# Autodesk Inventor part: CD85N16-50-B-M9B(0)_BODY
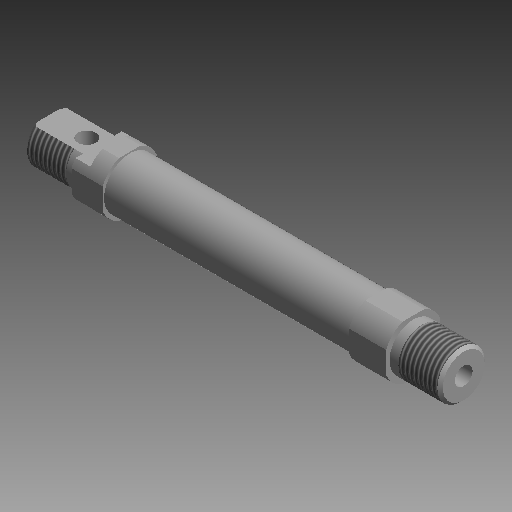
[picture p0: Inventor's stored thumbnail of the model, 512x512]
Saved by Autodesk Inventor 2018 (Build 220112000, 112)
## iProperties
Category: PARTsolutions
Company: SMC
Part Number: CD85N16-50-B-M9B(0)_BODY
Material: Generic
Catalog Web Link: www.cadenas.de
Description: C85/CD85 BODY-ISO Standard Air Cylinder:Standard Type Double Acting Single Rod
Vendor: SMC
Document SubType Name: Modeling
Designer: partserver
Manufacturer: SMC
Mass: 19.9773 g
Surface Area: 122.047 cm^2
Volume: 19.9773 cm^3
Density: 1 g/cm^3
Appearance: PSOLRGB-192-192-192
PSOL_IDENT_0: {$CADENAS_DATA\23d-libs\smc_jp\actuator\standard_air_cylinder\c85\c85\parts\c85_body.prj},247 {VTYP=
PSOL_IDENT_1: 3D},{NB=CD85N16-50-B-M9B(0)_BODY},{LINA=CD85N16-50-B-M9B_BODY},{NN=C85/CD85 BODY},{DATE=09.12.2020 0
PSOL_IDENT_2: 3:32:12},{GEOMDATE=26.04.2020 06:36:00},{VERSION=},{LINEID=90},{WBVAR=MAGNET,AUTOSW,STROKE,CUSHION,B
PSOL_IDENT_3: OOT,SWITCHMT,THREAD},{WBNUMERIC=STROKE}  {NB=CD85N16-50-B-M9B(0)_BODY},{LINA=CD85N16-50-B-M9B_BODY},
PSOL_IDENT_4: {KT=DUMMY},{ORDER=CD85N16-50-B-M9B},{BORE=16},{MOUNT=(N) Basic (Integral clevis)},{MOUNTX=N},{MAGNET=
PSOL_IDENT_5: D},{AUTOSW=-M9B},{AUTOSWX='','(-) Without auto switch','-M9N','M9N','-M9P','M9P','-M9B','M9B','-M9NV'
PSOL_IDENT_6: ,'M9NV','-M9PV','M9PV','-M9BV','M9BV','-M9NW','M9NW','-M9PW','M9PW','-M9BW','M9BW','-M9NWV','M9NWV','
PSOL_IDENT_7: -M9PWV','M9PWV','-M9BWV','M9BWV','-M9NA','M9NA','-M9PA','M9PA','-M9BA','M9BA','-M9NAV','M9NAV','-M9P
PSOL_IDENT_8: AV','M9PAV','-M9BAV','M9BAV','-A90','A90','-A93','A93','-A96','A96','-A90V','A90V','-A93V','A93V','-
PSOL_IDENT_9: A96V','A96V','-H7C','H7C','-H7NF','H7NF','-C73C','C73C','-C80C','C80C','-J79C','J79C','-F79F','F79F'
PSOL_IDENT_10: ,'-A72','A72','-A72H','A72H','-A73C','A73C','-A80C','A80C','-A79W','A79W'},{STROKE=50},{CUSHION=},{C
PSOL_IDENT_11: USHIONX= '','(-) Rubber bumper(Standard)','C','(C) Air cushion' },{BOOT=},{BOOTX= '','N/A' },{SWITCH
PSOL_IDENT_12: MT=-B},{SWITCHMTX= '-A','(A) Rail mounting','-B','(B) Band mounting' },{THREAD=0},{MAX=400},{MAX1=20
PSOL_IDENT_13: 0},{AM=16},{BE=M16x1.5},{BED=16},{BEJ=1.50},{C=6},{CD=6},{D=19.7},{EE=M5x0.8},{EW=12},{F=17},{G1=8},
PSOL_IDENT_14: {G2=6},{HR=14.0},{N1=12.5},{N2=10.5},{NA=18.3},{ND=16},{RR=13},{S=56},{U=9},{WA=9.5},{D1=17.400},{SW
PSOL_IDENT_15: A=7.5},{SWB=13.5},{SW=2}
NB: CD85N16-50-B-M9B(0)_BODY
NN: C85/CD85 BODY
NT: ISO Standard Air Cylinder:Standard Type Double Acting Single Rod
NBSYN: $ORDER.($THREAD.)_BODY
LINA: CD85N16-50-B-M9B_BODY
CATALOG: SMC (JP
BORE: 16
MOUNT: (N) Basic (Integral clevis)
MAGNET: (D) With magnet
AUTOSW: M9B
STROKE: 50
CUSHION: (-) Rubber bumper(Standard)
BOOT: N/A
SWITCHMT: (B) Band mounting
THREAD: on
MAX: 400
MAX1: 200
AM: 16
BE: M16x1.5
BED: 16
BEJ: 1.5
C: 6
CD: 6
D: 19.7
EE: M5x0.8
EW: 12
F: 17
HR: 14
NA: 18.3
ND: 16
RR: 13
U: 9
WA: 9.5
D1: 17.4
SUPPLIER: SMC
ARTICLENO: CD85N16-50-B-M9B(0)_BODY
BOMINFO: CD85N16-50-B-M9B_BODY
CREATOR: CADENAS GmbH
Title: CD85N16-50-B-M9B_BODY
Author: Cadenas PARTsolutions
Comments: ISO Standard Air Cylinder:Standard Type Double Acting Single Rod
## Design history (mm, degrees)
sketch "Sketch_1"
  geometry: L1 (106, 0)-(-17, 0); L2 (67.5, 0)-(67.5, 8); L3 (67.5, 8)-(12.5, 8); L4 (12.5, 8)-(12.5, 3); L5 (12.5, 3)-(-17, 3); L6 (-17, 3)-(-17, 7.08); L7 (-17, 7.08)-(-16.08, 8); L8 (-16.08, 8)-(0, 8); L9 (0, 8)-(0, 9.85); L10 (0, 9.85)-(12.5, 9.85); L11 (12.5, 9.85)-(12.5, 8.7); L12 (12.5, 8.7)-(95.5, 8.7); L13 (95.5, 8.7)-(95.5, 9.85); L14 (95.5, 9.85)-(106, 9.85); L15 (106, 9.85)-(106, 0); L16 (106, 0)-(67.5, 0)
  constraints: 32 end point
revolve "Revolution1" sketch "Sketch_1" stored, may be unused: angle "d0" = 360 deg
thread "Thread1" dims "d1" = 13.08, "d2" = 0
sketch "Sketch_2"
  geometry: L1 (3.647, 9.15)-(-3.647, 9.15); L2 (-9.15, 3.647)-(-9.15, -3.647); L3 (-3.647, -9.15)-(3.647, -9.15); L4 (9.15, -3.647)-(9.15, 3.647); C1 r 13.133 at (0, 0); A1 r 9.85 centre (0, 0) between (-3.647, 9.15) and (-9.15, 3.647); A2 r 9.85 centre (0, 0) between (-9.15, -3.647) and (-3.647, -9.15); A3 r 9.85 centre (0, 0) between (3.647, -9.15) and (9.15, -3.647); A4 r 9.85 centre (0, 0) between (9.15, 3.647) and (3.647, 9.15); 1 further point
  constraints: 8 end point, 8 point on circle, 5 centre point
extrude "Extrusion1" cut sketch "Sketch_2" distance "d3" = 111; taper "d4" = 0 deg
sketch "Sketch_3"
  geometry: L1 (8, 4.15)-(8, 9.15); L2 (8, 9.15)-(10.5, 9.15); L3 (10.5, 9.15)-(10.067, 8.717); L4 (10.067, 8.717)-(10.067, 4.15); L5 (10.067, 4.15)-(8, 2.957); L6 (8, 2.957)-(8, 9.15)
  constraints: 12 end point
revolve "Revolution2" sketch "Sketch_3" stored, may be unused: angle "d5" = 360 deg
thread "Thread2" dims "d6" = 4.567, "d7" = 0
sketch "Sketch_5"
  geometry: L1 (100, 4.15)-(100, 9.15); L2 (100, 9.15)-(102.5, 9.15); L3 (102.5, 9.15)-(102.067, 8.717); L4 (102.067, 8.717)-(102.067, 4.15); L5 (102.067, 4.15)-(100, 2.957); L6 (100, 2.957)-(100, 9.15)
  constraints: 12 end point
revolve "Revolution3" sketch "Sketch_5" stored, may be unused: angle "d8" = 360 deg
thread "Thread3" dims "d9" = 4.567, "d10" = 0
sketch "Sketch_13"
  geometry: L1 (123, 0)-(106, 0); L2 (106, 0)-(106, 8); L3 (106, 8)-(122.08, 8); L4 (122.08, 8)-(123, 7.08); L5 (123, 7.08)-(123, 0); L6 (123, 0)-(106, 0)
  constraints: 12 end point
revolve "Revolution4" sketch "Sketch_13" stored, may be unused: angle "d11" = 360 deg
thread "Thread4" dims "d12" = 13.08, "d13" = 0
sketch "Sketch_14"
  geometry: L1 (-101, -9.85)-(-101, -6); L2 (-101, -6)-(-123, -6); L3 (-123, -6)-(-123, 6); L4 (-123, 6)-(-101, 6); L5 (-101, 6)-(-101, 9.85); L6 (-101, 9.85)-(-128, 9.85); L7 (-128, 9.85)-(-128, -9.85); L8 (-128, -9.85)-(-101, -9.85)
  constraints: 16 end point
extrude "Extrusion2" cut sketch "Sketch_14" stored distance "d14" = 19.7; taper "d15" = 0 deg
sketch "Sketch_15"
  geometry: C1 r 3 at (110, 0); 1 further point
  constraints: 1 centre point
extrude "Extrusion3" cut sketch "Sketch_15" stored distance "d16" = 19.7; taper "d17" = 0 deg
node "BODY_XY"
node "BODY_YZ"
node "BODY_ZX"
node "BODY_X"
node "BODY_Y"
node "BODY_Z"
node "BODY_Center"
node "BODY_MNUT_XY"
node "BODY_MNUT_YZ"
node "BODY_MNUT_ZX"
node "BODY_MNUT_X"
node "BODY_MNUT_Y"
node "BODY_MNUT_Z"
node "BODY_MNUT_Center"
node "BODY_MNUT2_XY"
node "BODY_MNUT2_YZ"
node "BODY_MNUT2_ZX"
node "BODY_MNUT2_X"
node "BODY_MNUT2_Y"
node "BODY_MNUT2_Z"
node "BODY_MNUT2_Center"
node "Body_Bracket1_XY"
node "Body_Bracket1_YZ"
node "Body_Bracket1_ZX"
node "Body_Bracket1_X"
node "Body_Bracket1_Y"
node "Body_Bracket1_Z"
node "Body_Bracket1_Center"
node "Body_Bracket2_XY"
node "Body_Bracket2_YZ"
node "Body_Bracket2_ZX"
node "Body_Bracket2_X"
node "Body_Bracket2_Y"
node "Body_Bracket2_Z"
node "Body_Bracket2_Center"
node "Body_Clevis_XY"
node "Body_Clevis_YZ"
node "Body_Clevis_ZX"
node "Body_Clevis_X"
node "Body_Clevis_Y"
node "Body_Clevis_Z"
node "Body_Clevis_Center"
node "Body_SMA_Rail1_XY"
node "Body_SMA_Rail1_YZ"
node "Body_SMA_Rail1_ZX"
node "Body_SMA_Rail1_X"
node "Body_SMA_Rail1_Y"
node "Body_SMA_Rail1_Z"
node "Body_SMA_Rail1_Center"
node "Body_SMB_Rail2_XY"
node "Body_SMB_Rail2_YZ"
node "Body_SMB_Rail2_ZX"
node "Body_SMB_Rail2_X"
node "Body_SMB_Rail2_Y"
node "Body_SMB_Rail2_Z"
node "Body_SMB_Rail2_Center"
node "Body_SWA_Band1_XY"
node "Body_SWA_Band1_YZ"
node "Body_SWA_Band1_ZX"
node "Body_SWA_Band1_X"
node "Body_SWA_Band1_Y"
node "Body_SWA_Band1_Z"
node "Body_SWA_Band1_Center"
node "Body_SWB_Band2_XY"
node "Body_SWB_Band2_YZ"
node "Body_SWB_Band2_ZX"
node "Body_SWB_Band2_X"
node "Body_SWB_Band2_Y"
node "Body_SWB_Band2_Z"
node "Body_SWB_Band2_Center"
node "ND_1_XY"
node "ND_1_YZ"
node "ND_1_ZX"
node "ND_1_X"
node "ND_1_Y"
node "ND_1_Z"
node "ND_1_Center"
node "RR_XY"
node "RR_YZ"
node "RR_ZX"
node "RR_X"
node "RR_Y"
node "RR_Z"
node "RR_Center"
body "Solid1"
other parameters: "d18" = 0, "d19" = 0, "d20" = 0
